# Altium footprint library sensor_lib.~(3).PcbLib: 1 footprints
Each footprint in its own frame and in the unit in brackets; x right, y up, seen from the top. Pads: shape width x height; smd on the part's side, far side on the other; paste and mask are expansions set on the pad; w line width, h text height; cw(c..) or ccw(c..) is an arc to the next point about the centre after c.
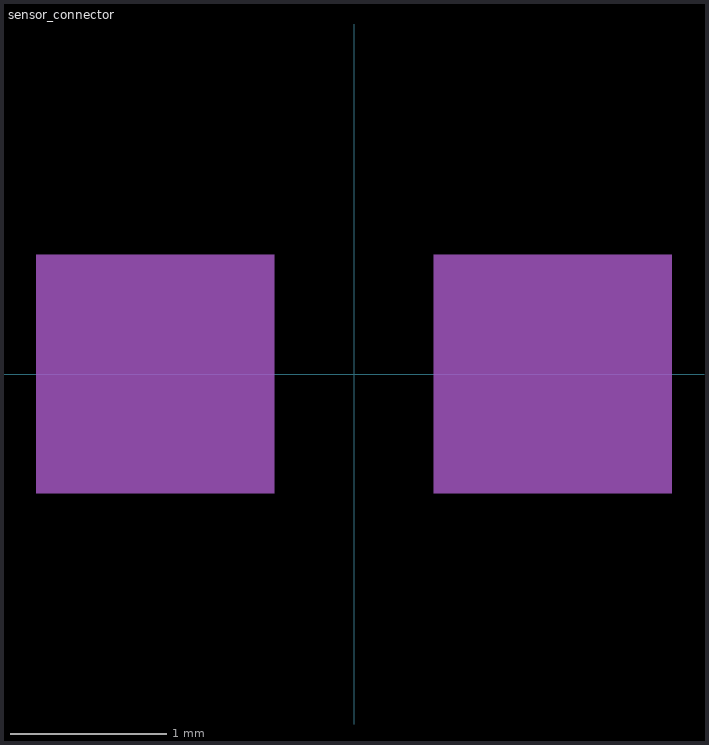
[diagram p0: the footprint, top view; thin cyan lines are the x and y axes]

## sensor_connector [mm]
Mechanical 1:
  rectangle: 0.508,-0.762 2.032,0.762
  rectangle: -2.032,-0.762 -0.508,0.762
